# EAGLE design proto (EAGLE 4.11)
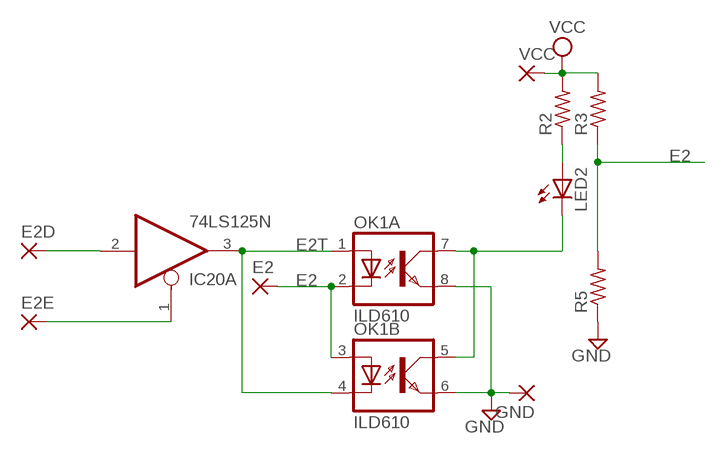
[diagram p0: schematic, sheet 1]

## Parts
E2  1,6/0,9  [1,6/0,9]
E2D  1,6/0,9  [1,6/0,9]
E2E  1,6/0,9  [1,6/0,9]
GND  1,6/0,9  [1,6/0,9]
IC20  74LS125N  [DIL14]
LED2  LED5MM  [LED5MM]
OK1  ILD610  [DIL08]
R2  R-US_0207/10  [0207/10]
R3  R-US_0207/10  [0207/10]
R5  R-US_0207/10  [0207/10]
VCC  1,6/0,9  [1,6/0,9]

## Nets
E2: E2.1(P) OK1.2(A:C) OK1.3(B:A) R3.1 R5.2
E2T: IC20.3(A:O) OK1.1(A:A) OK1.4(B:C)
GND [Power]: GND.1(P) OK1.6(B:EMIT) OK1.8(A:EMIT) R5.1
N$1: LED2.K(C) OK1.5(B:COL) OK1.7(A:COL)
N$4: LED2.A R2.1
N$59: E2D.1(P) IC20.2(A:I)
N$60: E2E.1(P) IC20.1(A:OE)
VCC [Power]: R2.2 R3.2 VCC.1(P)
Unconnected: IC20.4(B:OE) IC20.5(B:I) IC20.6(B:O) IC20.8(C:O) IC20.9(C:I) IC20.10(C:OE) IC20.11(D:O) IC20.12(D:I) IC20.13(D:OE)

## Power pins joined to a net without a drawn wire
GND: IC20.7(P:GND)
VCC: IC20.14(P:VCC)

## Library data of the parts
E2 E2D E2E GND VCC = wirepad:1,6/0,9: THROUGH-HOLE PAD
IC20 = 74xx-us:74*125: Quad bus BUFFER, 3-state
LED2 = led:LED: LED
OK1 = optocoupler:ILD610: SIEMENS OPTO COUPLER
R2 R3 R5 = rcl:R-US_: RESISTOR, American symbol

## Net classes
1 Power: width 0.508 mm, drill 0.254 mm, clearance 0.254 mm

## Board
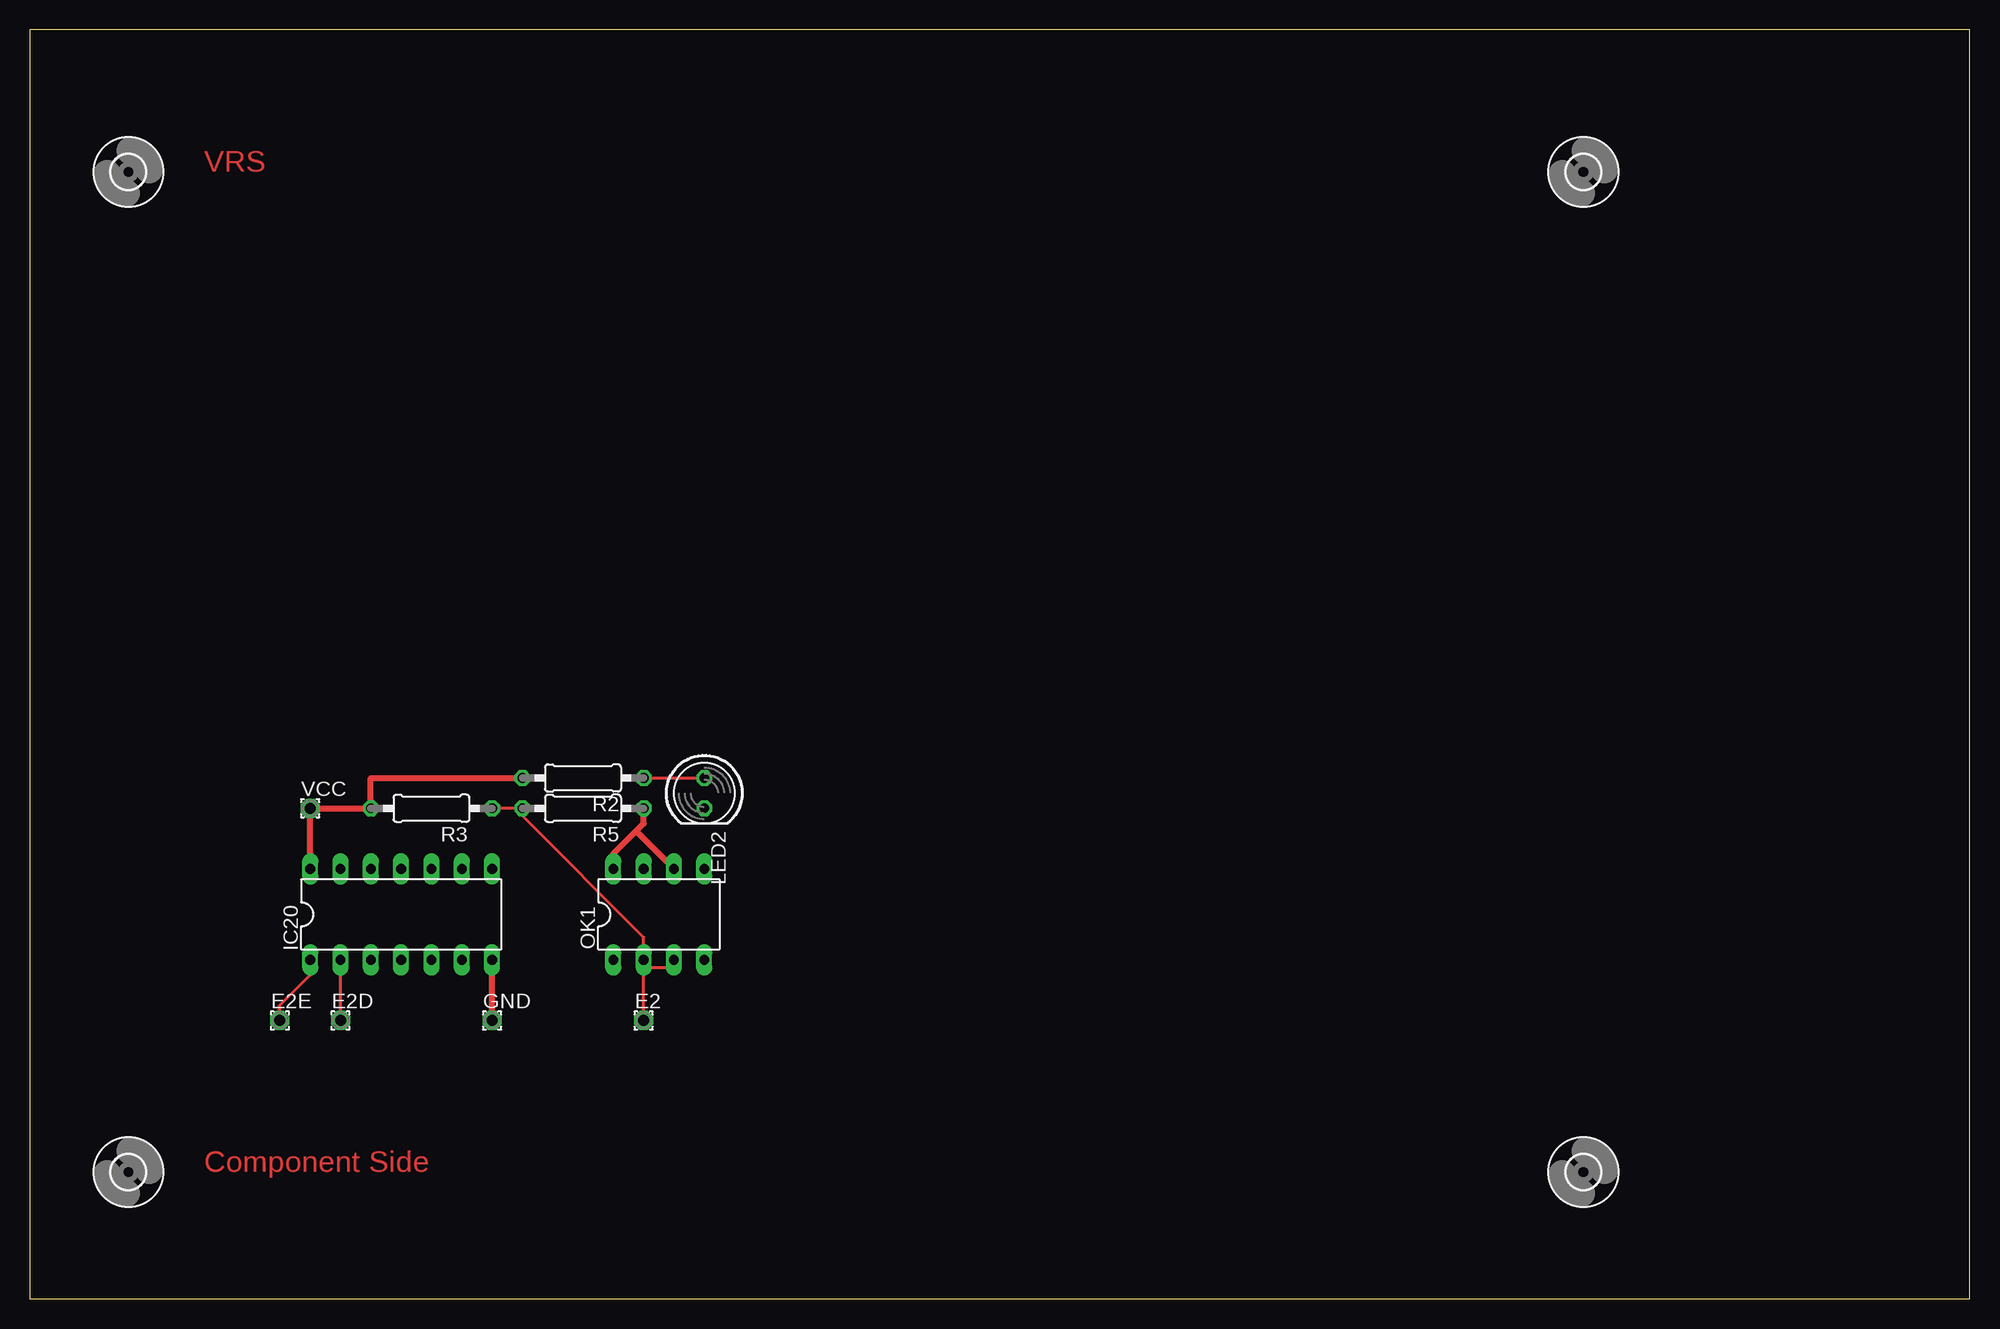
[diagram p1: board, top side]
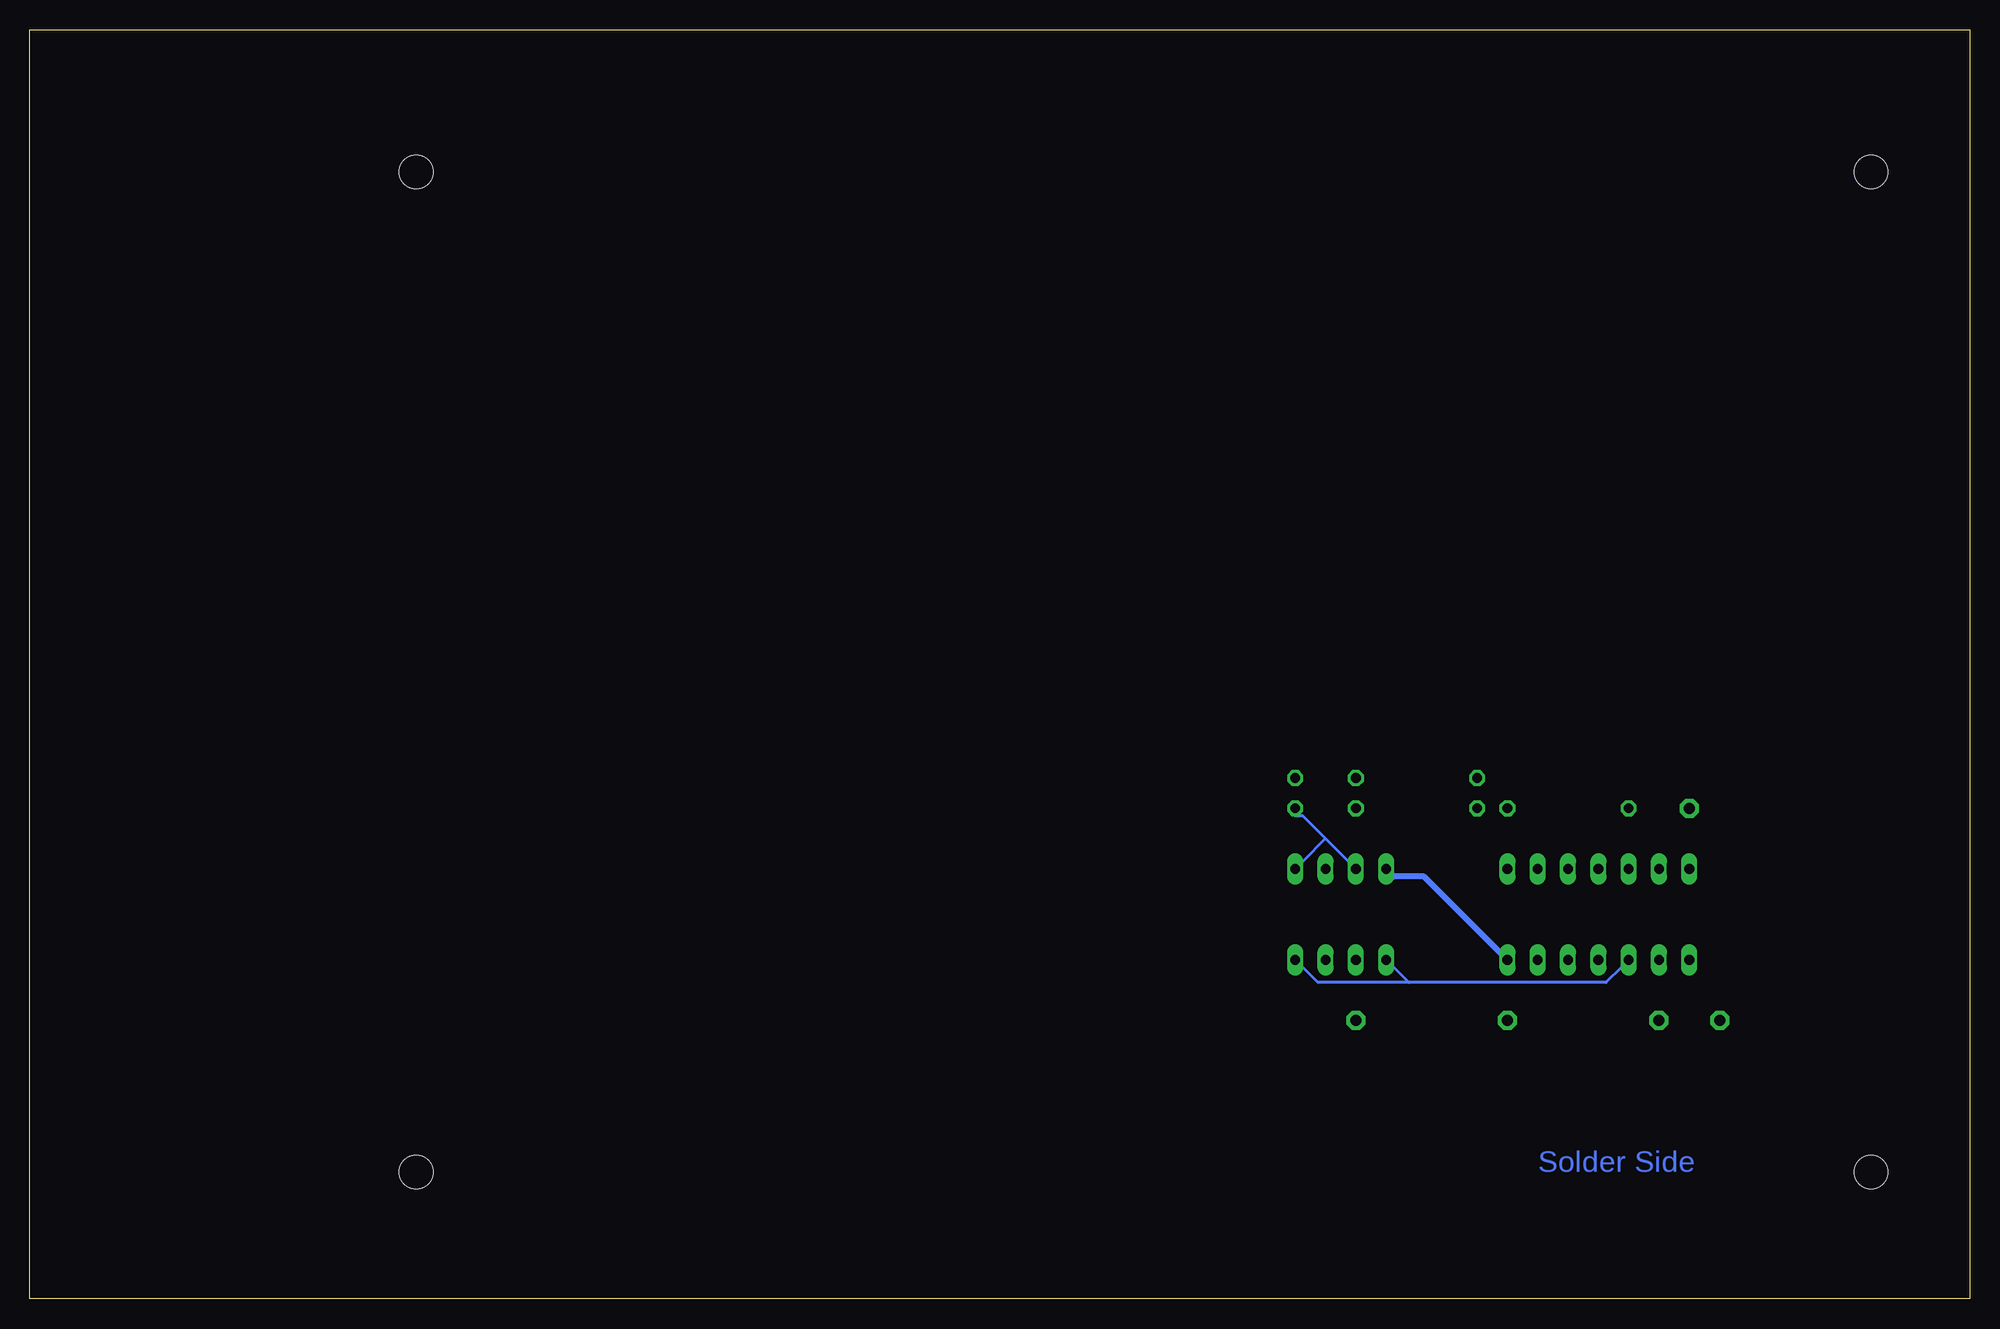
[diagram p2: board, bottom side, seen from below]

Size 162.54 x 106.35 mm. Coordinates in mm from the lower left corner, seen from the top.
Outline: 0,0 162.54,0 162.54,106.35 0,106.35 0,0
Copper layers (1*16): Top 0.035mm / dielectric 1.5mm / Bottom 0.035mm
Design rules "olimex10mil": minimum track width 10mil, minimum drill 24mil, track to track 10mil, track to pad 10mil, pad to pad 10mil, via to via 10mil, smd to smd 10mil, copper to edge 40mil, drill to drill 10mil, minimum pad ring 10mil, minimum via ring 8mil, stop-mask expansion 0mil, vias tented up to drill 0mil, thermal gap 10mil

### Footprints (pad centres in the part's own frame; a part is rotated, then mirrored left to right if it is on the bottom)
1,6/0,9 = drill 0.914 pad 1.6 octagon: 1 0,0
DIL14 = drill 0.813 long: 1 -7.62,-3.81; 2 -5.08,-3.81; 3 -2.54,-3.81; 4 0,-3.81; 5 2.54,-3.81; 6 5.08,-3.81; 7 7.62,-3.81; 8 7.62,3.81; 9 5.08,3.81; 10 2.54,3.81; 11 0,3.81; 12 -2.54,3.81; 13 -5.08,3.81; 14 -7.62,3.81
LED5MM = drill 0.813 octagon: A -1.27,0; K 1.27,0
DIL08 = drill 0.813 long: 1 -3.81,-3.81; 2 -1.27,-3.81; 3 1.27,-3.81; 4 3.81,-3.81; 5 3.81,3.81; 6 1.27,3.81; 7 -1.27,3.81; 8 -3.81,3.81
0207/10 = drill 0.813 octagon: 1 -5.08,0; 2 5.08,0
2,8 = hole 2.8: 0,0

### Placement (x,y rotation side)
E2  51.43,23.33 0 top
E2D  26.03,23.33 0 top
E2E  20.95,23.33 0 top
GND  38.73,23.33 0 top
IC20  31.11,32.22 0 top
LED2  56.51,42.38 270 top
OK1  52.7,32.22 0 top
R2  46.35,43.65 180 top
R3  33.65,41.11 180 top
R5  46.35,41.11 180 top
U$1  [2,8]  130.17,10.63 0 top
U$2  [2,8]  130.17,94.45 0 top
U$3  [2,8]  8.25,94.45 0 top
U$4  [2,8]  8.25,10.63 0 top
VCC  23.49,41.11 0 top

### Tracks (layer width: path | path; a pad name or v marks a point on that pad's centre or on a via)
E2
  Top 0.254: R3.1 39.37,41.11 40.63,41.11 R5.2 41.27,40.47 51.43,30.32 51.43,29.68 OK1.2 | OK1.2 52.06,27.77 53.34,27.77 OK1.3 | E2.1 51.43,23.96 51.43,27.14 OK1.2
E2T
  Bottom 0.254: 46.98,26.5 30.48,26.5 29.21,27.77 IC20.3 | 46.98,26.5 48.26,27.77 OK1.1 | 46.98,26.5 54.61,26.5 55.88,27.77 OK1.4
GND
  Top 0.508: IC20.7 38.73,27.14 38.73,23.96 GND.1 | 50.8,39.2 51.43,39.84 51.43,40.47 R5.1 | 50.8,39.2 48.89,37.3 OK1.8 | 50.8,39.2 53.34,36.66 OK1.6
  Bottom 0.508: IC20.7 39.37,29.04 45.72,35.39 48.26,35.39 OK1.8
N$1
  Bottom 0.254: 53.97,38.57 55.88,40.47 56.51,40.47 LED2.K | 53.97,38.57 52.06,36.66 OK1.7 | 53.97,38.57 55.88,36.66 OK1.5
N$4
  Top 0.254: R2.1 52.06,43.65 55.88,43.65 LED2.A
N$59
  Top 0.254: IC20.2 26.03,27.14 26.03,23.96 E2D.1
N$60
  Top 0.254: IC20.1 23.49,27.14 20.95,24.6 20.95,23.96 E2E.1
VCC
  Top 0.508: IC20.14 23.49,37.3 23.49,40.47 VCC.1 24.12,41.11 27.94,41.11 R3.2 28.57,41.75 28.57,43.65 40.63,43.65 R2.2

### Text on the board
Top: VRS | Component Side
Bottom: Solder Side
tValues: FlipChip Interface- Rev. 1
